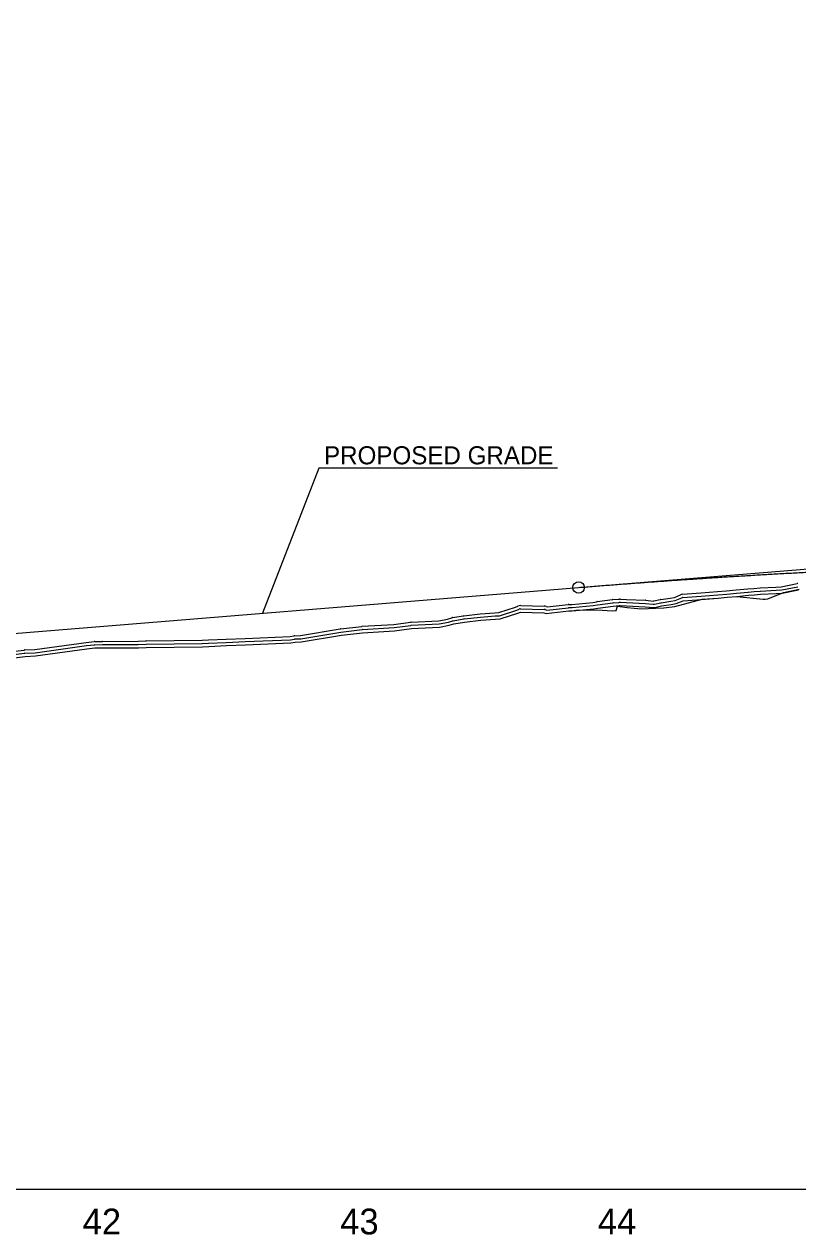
# Model space of a CAD drawing. Extents: x 1625686 to 1640492, y 1161393 to 1175642.
# Drawn here: x 1633374.4 to 1633674.2, y 1174893.1 to 1175362.5 of the extents above; entities that cross this region are included whole.
import ezdxf

# ---------------------------------------------------------------- set-up
doc = ezdxf.new("R2010")
doc.units = 0
for name, color, linetype in [('Exist Profile Cell', 7, 'Continuous'), ('Exist Vertical Profile Ground Line', 7, 'Continuous'), ('Exist Vertical Profile Horizontal Axis Label Major', 7, 'Continuous'), ('Prop Vertical Profile Curve Label', 7, 'Continuous'), ('Prop Vertical Profile Grade', 7, 'Continuous'), ('Prop VPI Label', 7, 'Continuous'), ('Scratch_Level_1', 7, 'Continuous'), ('Scratch_Level_3', 7, 'Continuous'), ('Scratch_Level_5', 7, 'Continuous')]:
    doc.layers.add(name, color=color, linetype=linetype)

msp = doc.modelspace()

# ---------------------------------------------------------------- linework, layer by layer
at = {"layer": 'Exist Profile Cell'}
msp.add_line((1630204.31, 1174910.79), (1634670.63, 1174910.79), dxfattribs=at)
at = {"layer": 'Exist Vertical Profile Ground Line'}
msp.add_lwpolyline([(1633367.51, 1175116.49), (1633374.73, 1175117.37), (1633378.78, 1175117.57), (1633398.72, 1175120.31), (1633401.85, 1175120.65), (1633404.74, 1175120.7), (1633418.66, 1175120.73), (1633421.73, 1175120.89), (1633443.49, 1175121.13), (1633445.92, 1175121.26), (1633452.78, 1175121.55), (1633460.13, 1175121.87), (1633477.79, 1175122.62), (1633479.39, 1175122.89), (1633481.71, 1175122.99), (1633497.34, 1175125.56), (1633505.58, 1175126.55), (1633517.95, 1175127.29), (1633524.5, 1175128.18), (1633535.41, 1175128.72), (1633539.12, 1175129.43), (1633540.88, 1175130), (1633545.04, 1175130.69), (1633551.36, 1175131.4), (1633557.03, 1175131.81), (1633558.89, 1175131.93), (1633565.75, 1175134.14), (1633566.78, 1175134.59), (1633575.88, 1175134.33), (1633576.78, 1175134.03), (1633585.52, 1175135.03), (1633586.79, 1175135.03), (1633588.17, 1175135.29), (1633596.36, 1175135.37), (1633602.47, 1175135.09), (1633603.79, 1175135.23), (1633604.36, 1175136.82), (1633608.07, 1175136.37), (1633610.8, 1175136.06), (1633613.63, 1175135.88), (1633619.16, 1175136.11), (1633622.33, 1175136.19), (1633626.54, 1175136.67), (1633637.14, 1175139.6), (1633643.35, 1175140), (1633646.84, 1175140.31), (1633650.62, 1175140.66), (1633660.85, 1175139.61), (1633661.65, 1175139.58), (1633662.68, 1175139.68), (1633668.68, 1175142.2), (1633674.79, 1175143.43)], dxfattribs=at)
at = {"layer": 'Prop Vertical Profile Curve Label'}
msp.add_circle((1633589.31, 1175144.1), 2.25, dxfattribs=at)
at = {"layer": 'Prop Vertical Profile Grade'}
msp.add_line((1633059.31, 1175100.98), (1633589.31, 1175144.1), dxfattribs=at)
msp.add_spline([(1633589.31, 1175144.1), (1633595.31, 1175144.58), (1633601.31, 1175145.05), (1633607.31, 1175145.51), (1633613.31, 1175145.96), (1633619.31, 1175146.39), (1633625.31, 1175146.82), (1633631.31, 1175147.23), (1633637.31, 1175147.63), (1633643.31, 1175148.02), (1633649.31, 1175148.4), (1633655.31, 1175148.76), (1633661.31, 1175149.12), (1633667.31, 1175149.46), (1633673.31, 1175149.79), (1633679.31, 1175150.11), (1633685.31, 1175150.42), (1633691.31, 1175150.72), (1633697.31, 1175151), (1633703.31, 1175151.28), (1633709.31, 1175151.54), (1633715.31, 1175151.79), (1633721.31, 1175152.03), (1633727.31, 1175152.25), (1633733.31, 1175152.47), (1633739.31, 1175152.67), (1633745.31, 1175152.86), (1633751.31, 1175153.04), (1633757.31, 1175153.21), (1633763.31, 1175153.37), (1633769.31, 1175153.52), (1633775.31, 1175153.65), (1633781.31, 1175153.77), (1633787.31, 1175153.88), (1633793.31, 1175153.98), (1633799.31, 1175154.07), (1633805.31, 1175154.14), (1633811.31, 1175154.21), (1633817.31, 1175154.26), (1633823.31, 1175154.3), (1633829.31, 1175154.33), (1633835.31, 1175154.35), (1633841.31, 1175154.36), (1633847.31, 1175154.35), (1633853.31, 1175154.33), (1633859.31, 1175154.31), (1633865.31, 1175154.27), (1633871.31, 1175154.21), (1633877.31, 1175154.15), (1633883.31, 1175154.07), (1633889.31, 1175153.99)], degree=3, dxfattribs=at)
at = {"layer": 'Prop VPI Label'}
for p, q in [((1633488.57, 1175190.41), (1633466.82, 1175134.13)), ((1633581.12, 1175190.41), (1633488.57, 1175190.41)), ((1633589.31, 1175144.1), (1633736.57, 1175156.08))]:
    msp.add_line(p, q, dxfattribs=at)
at = {"layer": 'Scratch_Level_1'}
for p, q in [((1633566.81, 1175135.84), (1633575.91, 1175135.58)), ((1633566.85, 1175137.09), (1633575.95, 1175136.83)), ((1633596.48, 1175138.61), (1633602.42, 1175139.38)), ((1633596.64, 1175137.37), (1633602.58, 1175138.14)), ((1633602.54, 1175139.39), (1633604.78, 1175139.58)), ((1633602.64, 1175138.15), (1633604.88, 1175138.33)), ((1633604.81, 1175139.58), (1633605.18, 1175139.6)), ((1633604.89, 1175138.33), (1633605.26, 1175138.36)), ((1633540.47, 1175132.47), (1633544.63, 1175133.16)), ((1633540.68, 1175131.23), (1633544.83, 1175131.92)), ((1633544.76, 1175133.17), (1633551.09, 1175133.88)), ((1633544.9, 1175131.93), (1633551.22, 1175132.64)), ((1633551.18, 1175133.89), (1633556.85, 1175134.3)), ((1633551.27, 1175132.64), (1633556.94, 1175133.06)), ((1633497.05, 1175128.05), (1633505.28, 1175129.03)), ((1633497.19, 1175126.81), (1633505.43, 1175127.79)), ((1633398.45, 1175122.8), (1633401.58, 1175123.13)), ((1633398.58, 1175121.55), (1633401.72, 1175121.89)), ((1633401.8, 1175123.15), (1633404.69, 1175123.2)), ((1633401.83, 1175121.9), (1633404.71, 1175121.95))]:
    msp.add_line(p, q, dxfattribs=at)
for points in [[(1633659.67, 1175143.94), (1633665.78, 1175144.26), (1633667.86, 1175144.37), (1633673.99, 1175145.62)], [(1633659.73, 1175142.7), (1633665.85, 1175143.01), (1633668.02, 1175143.13), (1633674.24, 1175144.39)], [(1633621.1, 1175139.42), (1633624.84, 1175139.97), (1633626.41, 1175140.24), (1633628.83, 1175141.27)], [(1633621.28, 1175138.19), (1633625.03, 1175138.74), (1633626.77, 1175139.04), (1633629.31, 1175140.12)], [(1633629.62, 1175141.46), (1633636.64, 1175141.98), (1633643.14, 1175142.49), (1633646.61, 1175142.8), (1633650.38, 1175143.15), (1633654.88, 1175143.59)], [(1633629.71, 1175140.21), (1633636.74, 1175140.73), (1633643.24, 1175141.24), (1633646.73, 1175141.56), (1633650.5, 1175141.91), (1633655, 1175142.34)], [(1633654.93, 1175143.59), (1633657.25, 1175143.76), (1633659.6, 1175143.94)], [(1633655.03, 1175142.34), (1633657.34, 1175142.51), (1633659.7, 1175142.69)], [(1633556.87, 1175134.31), (1633558.42, 1175134.4), (1633564.86, 1175136.48), (1633565.77, 1175136.88)], [(1633556.95, 1175133.06), (1633558.65, 1175133.16), (1633565.3, 1175135.31), (1633566.27, 1175135.74)], [(1633576.28, 1175135.52), (1633576.92, 1175135.3), (1633585.37, 1175136.27)], [(1633576.67, 1175136.7), (1633577.05, 1175136.58), (1633585.23, 1175137.51)], [(1633585.52, 1175137.53), (1633586.68, 1175137.53), (1633594.8, 1175138.29), (1633596.33, 1175138.59)], [(1633585.52, 1175136.28), (1633586.74, 1175136.28), (1633594.98, 1175137.05), (1633596.57, 1175137.36)], [(1633605.41, 1175138.36), (1633607.86, 1175138.24), (1633615.16, 1175137.9)], [(1633605.48, 1175139.61), (1633607.92, 1175139.48), (1633615.22, 1175139.15)], [(1633615.24, 1175137.89), (1633618.24, 1175137.58), (1633618.71, 1175137.63), (1633621.2, 1175138.17)], [(1633615.36, 1175139.14), (1633618.24, 1175138.84), (1633618.51, 1175138.87), (1633620.94, 1175139.39)], [(1633505.43, 1175129.04), (1633517.71, 1175129.78), (1633524.16, 1175130.66)], [(1633524.38, 1175130.68), (1633535.12, 1175131.21), (1633538.49, 1175131.85), (1633540.11, 1175132.38)], [(1633524.44, 1175129.43), (1633535.27, 1175129.97), (1633538.81, 1175130.64), (1633540.49, 1175131.19)], [(1633479.28, 1175125.39), (1633481.46, 1175125.48), (1633496.94, 1175128.03)], [(1633479.33, 1175124.14), (1633481.58, 1175124.23), (1633497.14, 1175126.8)], [(1633505.51, 1175127.79), (1633517.83, 1175128.53), (1633524.33, 1175129.42)], [(1633374.61, 1175119.87), (1633378.54, 1175120.06), (1633398.38, 1175122.79)], [(1633374.67, 1175118.62), (1633378.66, 1175118.81), (1633398.55, 1175121.55)], [(1633404.73, 1175123.2), (1633418.6, 1175123.23), (1633421.6, 1175123.39)], [(1633404.73, 1175121.95), (1633418.63, 1175121.98), (1633421.67, 1175122.14)], [(1633421.7, 1175123.39), (1633443.41, 1175123.63), (1633445.79, 1175123.76)], [(1633421.71, 1175122.14), (1633443.45, 1175122.38), (1633445.86, 1175122.51)], [(1633445.82, 1175123.76), (1633452.68, 1175124.05), (1633460.03, 1175124.37)], [(1633445.87, 1175122.51), (1633452.73, 1175122.8), (1633460.08, 1175123.12)], [(1633460.03, 1175124.37), (1633477.53, 1175125.11), (1633478.96, 1175125.36)], [(1633460.08, 1175123.12), (1633477.66, 1175123.86), (1633479.17, 1175124.12)], [(1633366.26, 1175118.97), (1633367.33, 1175118.99), (1633374.42, 1175119.85)], [(1633366.28, 1175117.72), (1633367.42, 1175117.74), (1633374.58, 1175118.61)]]:
    msp.add_lwpolyline(points, dxfattribs=at)
for centre, radius, start, end in [((1633674.49, 1175143.17), 2.5, 94.1965, 101.4805), ((1633629.8, 1175138.96), 2.5, 94.2508, 112.9541), ((1633629.8, 1175138.96), 1.25, 94.2508, 112.9541), ((1633655.12, 1175141.1), 2.5, 94.2169, 95.4818), ((1633655.12, 1175141.1), 1.25, 94.2169, 95.4818), ((1633659.79, 1175141.45), 2.5, 92.9168, 94.3822), ((1633659.79, 1175141.45), 1.25, 92.9168, 94.3822), ((1633566.78, 1175134.59), 2.5, 88.3729, 113.7703), ((1633566.78, 1175134.59), 1.25, 88.3729, 113.7703), ((1633575.88, 1175134.33), 1.25, 71.3999, 88.3729), ((1633575.88, 1175134.33), 2.5, 71.3999, 88.3729), ((1633585.52, 1175135.03), 2.5, 89.8778, 96.536), ((1633585.52, 1175135.03), 1.25, 89.8778, 96.536), ((1633596.8, 1175136.13), 2.5, 97.3926, 100.858), ((1633596.8, 1175136.13), 1.25, 97.3926, 100.858), ((1633602.74, 1175136.9), 2.5, 94.6193, 97.3926), ((1633602.74, 1175136.9), 1.25, 94.6193, 97.3926), ((1633604.98, 1175137.08), 2.5, 93.9476, 94.6193), ((1633604.98, 1175137.08), 1.25, 93.9476, 94.6193), ((1633605.35, 1175137.11), 2.5, 87.1466, 93.9476), ((1633605.35, 1175137.11), 1.25, 87.1466, 93.9476), ((1633615.11, 1175136.65), 1.25, 84.1047, 87.3612), ((1633615.11, 1175136.65), 2.5, 84.1047, 87.3612), ((1633621.46, 1175136.95), 2.5, 98.3239, 102.1934), ((1633621.46, 1175136.95), 1.25, 98.3239, 102.1934), ((1633524.5, 1175128.18), 2.5, 92.8256, 97.7721), ((1633540.88, 1175130), 2.5, 99.421, 107.9697), ((1633540.88, 1175130), 1.25, 99.421, 107.9697), ((1633545.04, 1175130.69), 2.5, 96.3811, 99.421), ((1633545.04, 1175130.69), 1.25, 96.3811, 99.421), ((1633551.36, 1175131.4), 2.5, 94.1736, 96.3811), ((1633551.36, 1175131.4), 1.25, 94.1736, 96.3811), ((1633557.03, 1175131.81), 2.5, 93.5481, 94.1736), ((1633557.03, 1175131.81), 1.25, 93.5481, 94.1736), ((1633497.34, 1175125.56), 2.5, 96.7976, 99.3617), ((1633497.34, 1175125.56), 1.25, 96.7976, 99.3617), ((1633505.58, 1175126.55), 2.5, 93.4365, 96.7976), ((1633505.58, 1175126.55), 1.25, 93.4365, 96.7976), ((1633524.5, 1175128.18), 1.25, 92.8256, 97.7721), ((1633398.72, 1175120.31), 2.5, 96.1185, 97.8277), ((1633398.72, 1175120.31), 1.25, 96.1185, 97.8277), ((1633401.85, 1175120.65), 2.5, 91.0814, 96.1185), ((1633401.85, 1175120.65), 1.25, 91.0814, 96.1185), ((1633404.74, 1175120.7), 2.5, 90.1366, 91.0814), ((1633404.74, 1175120.7), 1.25, 90.1366, 91.0814), ((1633421.73, 1175120.89), 2.5, 90.6378, 92.9195), ((1633421.73, 1175120.89), 1.25, 90.6378, 92.9195), ((1633445.92, 1175121.26), 2.5, 92.4366, 93.0502), ((1633445.92, 1175121.26), 1.25, 92.4366, 93.0502), ((1633460.13, 1175121.87), 2.5, 92.432, 92.4462), ((1633460.13, 1175121.87), 1.25, 92.432, 92.4462), ((1633479.39, 1175122.89), 2.5, 92.3737, 99.7421), ((1633479.39, 1175122.89), 1.25, 92.3737, 99.7421), ((1633374.73, 1175117.37), 2.5, 92.7936, 96.9762), ((1633374.73, 1175117.37), 1.25, 92.7936, 96.9762)]:
    msp.add_arc(centre, radius, start, end, dxfattribs=at)
at = {"layer": 'Scratch_Level_3'}
msp.add_lwpolyline([(1630204.31, 1174910.79), (1634341.72, 1174910.79), (1634341.72, 1175362.47)], dxfattribs=at)
at = {"layer": 'Scratch_Level_5'}
msp.add_lwpolyline([(1633367.51, 1175116.49), (1633374.73, 1175117.37), (1633378.78, 1175117.57), (1633398.72, 1175120.31), (1633401.85, 1175120.65), (1633404.74, 1175120.7), (1633418.66, 1175120.73), (1633421.73, 1175120.89), (1633443.49, 1175121.13), (1633445.92, 1175121.26), (1633452.78, 1175121.55), (1633460.13, 1175121.87), (1633477.79, 1175122.62), (1633479.39, 1175122.89), (1633481.71, 1175122.99), (1633497.34, 1175125.56), (1633505.58, 1175126.55), (1633517.95, 1175127.29), (1633524.5, 1175128.18), (1633535.41, 1175128.72), (1633539.12, 1175129.43), (1633540.88, 1175130), (1633545.04, 1175130.69), (1633551.36, 1175131.4), (1633557.03, 1175131.81), (1633558.89, 1175131.93), (1633565.75, 1175134.14), (1633566.78, 1175134.59), (1633575.88, 1175134.33), (1633576.78, 1175134.03), (1633585.52, 1175135.03), (1633586.79, 1175135.03), (1633595.16, 1175135.82), (1633596.8, 1175136.13), (1633602.74, 1175136.9), (1633604.98, 1175137.08), (1633605.35, 1175137.11), (1633607.8, 1175136.99), (1633615.11, 1175136.65), (1633618.24, 1175136.33), (1633618.9, 1175136.4), (1633621.46, 1175136.95), (1633625.23, 1175137.5), (1633627.12, 1175137.83), (1633629.8, 1175138.96), (1633636.83, 1175139.49), (1633643.35, 1175140), (1633646.84, 1175140.31), (1633650.62, 1175140.66), (1633655.12, 1175141.1), (1633657.44, 1175141.27), (1633659.79, 1175141.45), (1633665.91, 1175141.76), (1633668.18, 1175141.89), (1633674.49, 1175143.17)], dxfattribs=at)

# ---------------------------------------------------------------- texts
at = {"layer": 'Exist Vertical Profile Horizontal Axis Label Major'}
for s, p in [('42', (1633397.09, 1174893.29)), ('43', (1633496.92, 1174893.29)), ('44', (1633596.77, 1174893.29))]:
    msp.add_text(s, height=10, dxfattribs=at).set_placement(p)
at = {"layer": 'Prop VPI Label'}
msp.add_text('PROPOSED GRADE', height=7, dxfattribs=at).set_placement((1633490.62, 1175191.85))

doc.saveas('drawing.dxf')
